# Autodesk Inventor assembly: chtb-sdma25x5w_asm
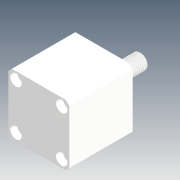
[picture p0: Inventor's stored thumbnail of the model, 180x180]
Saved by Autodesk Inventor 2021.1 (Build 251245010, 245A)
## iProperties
Company: Microsoft
Created: 2018-05
Part Number: chtb-sdma25x5w_asm
Description: STEP AP214
Document SubType Name: Assembly
Designer: user
Title: chtb-sdma25x5w_asm.STEP
Author: Windows
Revision Number: ÈÎºÎ
Sending System: SolidWorks 2015
Preprocessor: SwSTEP 2.0
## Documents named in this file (4)
- D:\Vault_2016\Projekty\Clamptek\Hydraulic\CHTB\CHTB-25\Inventor\chtb-sdma25x5w\chtb-sdma25x5w_asm.iam
- D:\Vault_2016\Projekty\Clamptek\Hydraulic\CHTB\CHTB-25\Inventor\chtb-sdma25x5w\CHTB-25QG.ipt
- D:\Vault_2016\Projekty\Clamptek\Hydraulic\CHTB\CHTB-25\Inventor\chtb-sdma25x5w\CHTB-SDMA25X5NBT.ipt
- D:\Vault_2016\Projekty\Clamptek\Hydraulic\CHTB\CHTB-25\Inventor\chtb-sdma25x5w\CHTB-SDMA25X5WHSG.ipt
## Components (3 placed, 3 different names)
1. CHTB-25QG_1
2. CHTB-SDMA25X5NBT_2
3. CHTB-SDMA25X5WHSG_3
